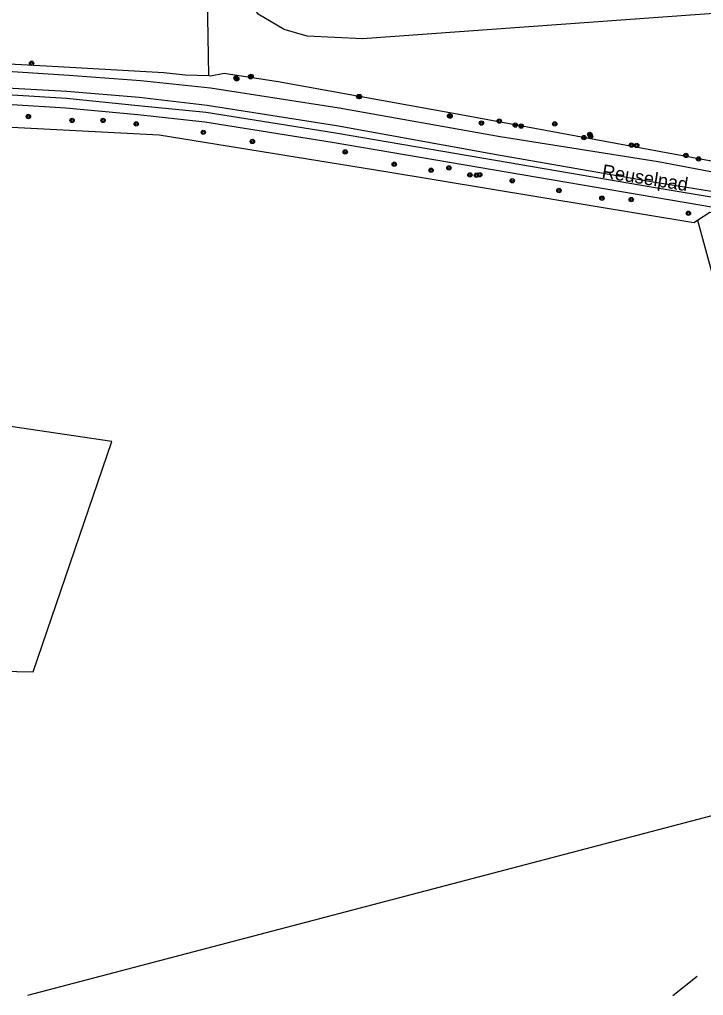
# Model space of a CAD drawing. Extents: x 128999 to 131010, y 395498 to 399007.
# Drawn here: x 130043.8 to 130169.9, y 395500 to 395680 of the extents above; entities that cross this region are included whole.
import ezdxf

# ---------------------------------------------------------------- set-up
doc = ezdxf.new("R2010")
doc.units = 0
for name, color, linetype in [('gg-afsc-draadraster', 7, 'Continuous'), ('gg-anno-openbare ruimte label', 7, 'Continuous'), ('gg-knt-onverhard', 7, 'Continuous'), ('gg-knt-verharding', 7, 'Continuous'), ('gg-knt-verharding nz', 7, 'Continuous'), ('gt-grn-groengrens', 7, 'Continuous'), ('gt-symb-boom', 7, 'Continuous')]:
    doc.layers.add(name, color=color, linetype=linetype)

# ---------------------------------------------------------------- blocks, each defined once
blk = doc.blocks.new('gt0-BOOM')
at = {"layer": 'gt-symb-boom'}
for radius in [0.4, 0.2]:
    blk.add_circle((0, 0), radius, dxfattribs=at)

msp = doc.modelspace()

# ---------------------------------------------------------------- linework, layer by layer
at = {"layer": 'gg-afsc-draadraster'}
for points in [[(129925.24, 395678.7), (129975.47, 395675.72), (130004.32, 395673.89), (130049.78, 395671.41), (130070.35, 395670.27), (130074.3, 395669.84), (130078.65, 395669.68)], [(130078.65, 395669.68), (130078.97, 395669.66), (130081.52, 395670.11), (130091.49, 395668.57), (130125.13, 395662.49), (130254.45, 395638.6), (130301.9, 395630.58), (130306.17, 395630.25)], [(129941.68, 395665.28), (129975.42, 395663.6), (130033.99, 395660.58), (130069.54, 395658.77), (130111.33, 395651.99), (130168.13, 395642.6), (130168.79, 395643.02)], [(130168.79, 395643.02), (130171.08, 395644.48), (130252.27, 395630.54), (130313.51, 395620.05), (130313.2, 395617.28), (130200.2, 395529.05), (130194.17, 395523.14)], [(130005.5, 395581.42), (130004.3, 395560.54), (130046.29, 395559.72), (130060.81, 395602.17), (130006.72, 395610.19), (130006.35, 395598.41)]]:
    msp.add_lwpolyline(points, dxfattribs=at)
at = {"layer": 'gg-knt-onverhard'}
for points in [[(130151.62, 395834.75), (130151.63, 395811.47), (130191.51, 395761.34), (130217.53, 395727.34), (130234.52, 395703.42), (130237.97, 395695.07), (130232.07, 395684.98), (130217.55, 395682.22), (130174.36, 395681.35), (130107.02, 395676.45), (130096.82, 395676.93), (130092.54, 395678.16), (130087.77, 395681.04), (130084.48, 395686.31), (130083.99, 395693.8), (130086.12, 395699.4)], [(129925.24, 395678.7), (129925.27, 395677.45), (129925.91, 395676.55), (129946.73, 395674.93), (129972.25, 395673.6), (130002.69, 395672.25), (130032.96, 395671.04), (130052.85, 395669.77), (130066.11, 395668.8), (130079.01, 395667.45), (130102.73, 395663.72), (130132.42, 395658.48), (130161.52, 395653.81), (130192.01, 395648.05), (130220.65, 395643.05), (130250.79, 395637.41), (130279.68, 395632.59), (130308.5, 395628.79), (130313.59, 395628.25)], [(130312.03, 395623.72), (130308.53, 395624.78), (130279.13, 395629.6), (130250.31, 395634.54), (130220.11, 395639.8), (130191.38, 395645.11), (130160.62, 395650.03), (130131.71, 395655.04), (130102.19, 395660.42), (130078.35, 395664.15), (130065.82, 395665.62), (130052.46, 395666.73), (130032.51, 395667.85), (130002.64, 395669.18), (129972.15, 395670.41), (129946.64, 395671.68), (129924.6, 395672.67), (129905.36, 395674.11), (129881.11, 395675.16), (129853.63, 395676.24), (129833.36, 395676.5)]]:
    msp.add_lwpolyline(points, dxfattribs=at)
at = {"layer": 'gg-knt-verharding'}
for points in [[(129833.36, 395676.5), (129853.55, 395675.21), (129881.18, 395673.82), (129905.33, 395672.56), (129924.63, 395671.57), (129972.23, 395669.22), (130002.64, 395668.04), (130032.45, 395666.75), (130052.44, 395665.52), (130065.67, 395664.19), (130078.21, 395662.95), (130102.04, 395659.14), (130131.55, 395654.07), (130160.65, 395649.12), (130191.16, 395643.99), (130219.97, 395639.03), (130250.25, 395633.75), (130279.05, 395628.82), (130308.47, 395623.83), (130310.08, 395623.57), (130312.03, 395623.72)], [(130313.21, 395621.71), (130310.83, 395621.61), (130308.31, 395621.75), (130278.8, 395626.91), (130249.91, 395631.93), (130219.74, 395637.12), (130190.85, 395642.11), (130101.44, 395657.36), (130077.91, 395661.09), (130065.59, 395662.45), (130052.32, 395663.67), (130032.42, 395664.93), (130002.6, 395666.12), (129972.32, 395667.4), (129946.47, 395668.52), (129924.26, 395669.56), (129881.31, 395671.84), (129853.47, 395673.2), (129832.66, 395674.67)]]:
    msp.add_lwpolyline(points, dxfattribs=at)
at = {"layer": 'gg-knt-verharding nz'}
msp.add_line((130164.24, 395500), (130168.74, 395503.56), dxfattribs=at)
at = {"layer": 'gt-grn-groengrens'}
msp.add_line((130078.65, 395669.68), (130072.68, 396077.49), dxfattribs=at)
msp.add_lwpolyline([(130168.79, 395643.02), (130196.94, 395539.83), (130045.21, 395500)], dxfattribs=at)

# ---------------------------------------------------------------- block references
at = {"layer": 'gt-symb-boom'}
for p in [(130045.98, 395671.97), (130083.7, 395669.25), (130083.81, 395669.09), (130086.36, 395669.48), (130086.48, 395669.53), (130106.32, 395665.8), (130106.46, 395665.8), (130045.4, 395662.14), (130053.46, 395661.43), (130059.17, 395661.43), (130065.3, 395660.78), (130123.09, 395662.25), (130123.18, 395662.23), (130128.96, 395660.94), (130132.24, 395661.31), (130135.2, 395660.56), (130142.47, 395660.78), (130077.66, 395659.22), (130136.28, 395660.38), (130148.93, 395658.84), (130086.72, 395657.53), (130147.86, 395658.25), (130149.08, 395658.49), (130103.82, 395655.61), (130156.62, 395656.88), (130157.59, 395656.81), (130112.86, 395653.33), (130166.66, 395654.96), (130168.99, 395654.31), (130119.67, 395652.22), (130122.96, 395652.65), (130126.82, 395651.36), (130128.03, 395651.29), (130128.64, 395651.4), (130134.63, 395650.28), (130143.25, 395648.49), (130151.18, 395647.07), (130156.57, 395646.8), (130167.12, 395644.29)]:
    msp.add_blockref('gt0-BOOM', p, dxfattribs=at)

# ---------------------------------------------------------------- texts
at = {"layer": 'gg-anno-openbare ruimte label'}
msp.add_text('Reuselpad', height=2.5, rotation=350.9, dxfattribs=at).set_placement((130151.05, 395650.88))

doc.saveas('drawing.dxf')
